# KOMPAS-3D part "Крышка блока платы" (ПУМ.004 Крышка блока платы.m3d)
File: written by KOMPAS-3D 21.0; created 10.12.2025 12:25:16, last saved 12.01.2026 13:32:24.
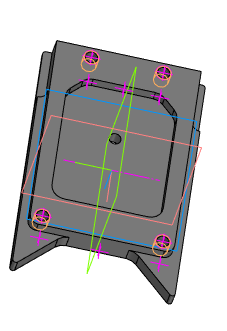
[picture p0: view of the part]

Document properties: Автор: User; Полное имя файла: C:\Users\User\Desktop\ПУ\ПУМ\ПУМ.004 Крышка блока платы.m3d

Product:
- Part/product: Крышка блока платы
    Материал: АМг6  ГОСТ 4784-2019 (density 2650 kg/m3)
    Масса: 0.073379

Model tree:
1. Эскиз:1
2. Элемент выдавливания:1
     Расстояние 1 = 9.5
3. Скругление:2  (with: Элемент выдавливания:1)
     Радиус = 5
4. Эскиз:4  (with: Элемент выдавливания:1)
5. Элемент выдавливания:11
     Расстояние 2 = 4
6. Скругление:6  (with: Элемент выдавливания:11)
     Радиус = 3
7. Эскиз:9  (with: Элемент выдавливания:1, Элемент выдавливания:3)
8. Элемент выдавливания:12
     Расстояние 2 = 5
9. Эскиз:10  (with: Элемент выдавливания:1)
10. Эскиз:11  (with: Элемент выдавливания:1, Отверстие:1)  (labels: Основание 1; Отверстие:1 Блок платы М5 потай)
11. Эскиз:12  (with: Элемент выдавливания:1)
12. Отверстие:1  (with: Элемент выдавливания:1, Элемент выдавливания:11)  (labels: M5)
     Глубина выреза = 7; Диаметр отверстия = 4.13397; Угол конуса дна = 118; Расстояние 1 = 3.5; Расстояние 2 = -44
13. M5  (with: Элемент выдавливания:1)  (labels: M5; cil0_24705-2004 coarse)
     Длина резьбы = 5; Шаг резьбы = 0.8; Номинальный диаметр резьбы = 5
14. Массив по точкам:1
15. Экземпляр ( 1 )  (with: Отверстие:1)  (labels: M5)
16. Экземпляр ( 2 )  (with: Отверстие:1)  (labels: M5)
17. Экземпляр ( 3 )  (with: Отверстие:1)  (labels: M5)
18. Скругление:7  (with: Элемент выдавливания:1)
     Радиус = 1
19. Фаска:4  (with: Элемент выдавливания:1)
     Угол = 45; Длина 1 = 0.2; Длина 2 = 0.2
20. Эскиз:13  (with: Элемент выдавливания:11, Элемент выдавливания:1)
21. Элемент выдавливания:13
     Расстояние 2 = 4
22. Скругление:8  (with: Элемент выдавливания:13)
     Радиус = 3
23. Эскиз:14  (with: Элемент выдавливания:1, Элемент выдавливания:3)
24. Элемент выдавливания:14
     Расстояние 2 = 4
25. Эскиз:15  (with: Элемент выдавливания:1)
26. Элемент выдавливания:15
     Расстояние 2 = 10
27. Эскиз:16  (with: Элемент выдавливания:1)
28. Элемент выдавливания:16  (labels: АМг6  ГОСТ 4784-2019)
     Расстояние 2 = 0.2

Referenced files in C:\Users\User\Desktop\ПУ\ПУМ\: ПУМ.000.00 Сборка.a3d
